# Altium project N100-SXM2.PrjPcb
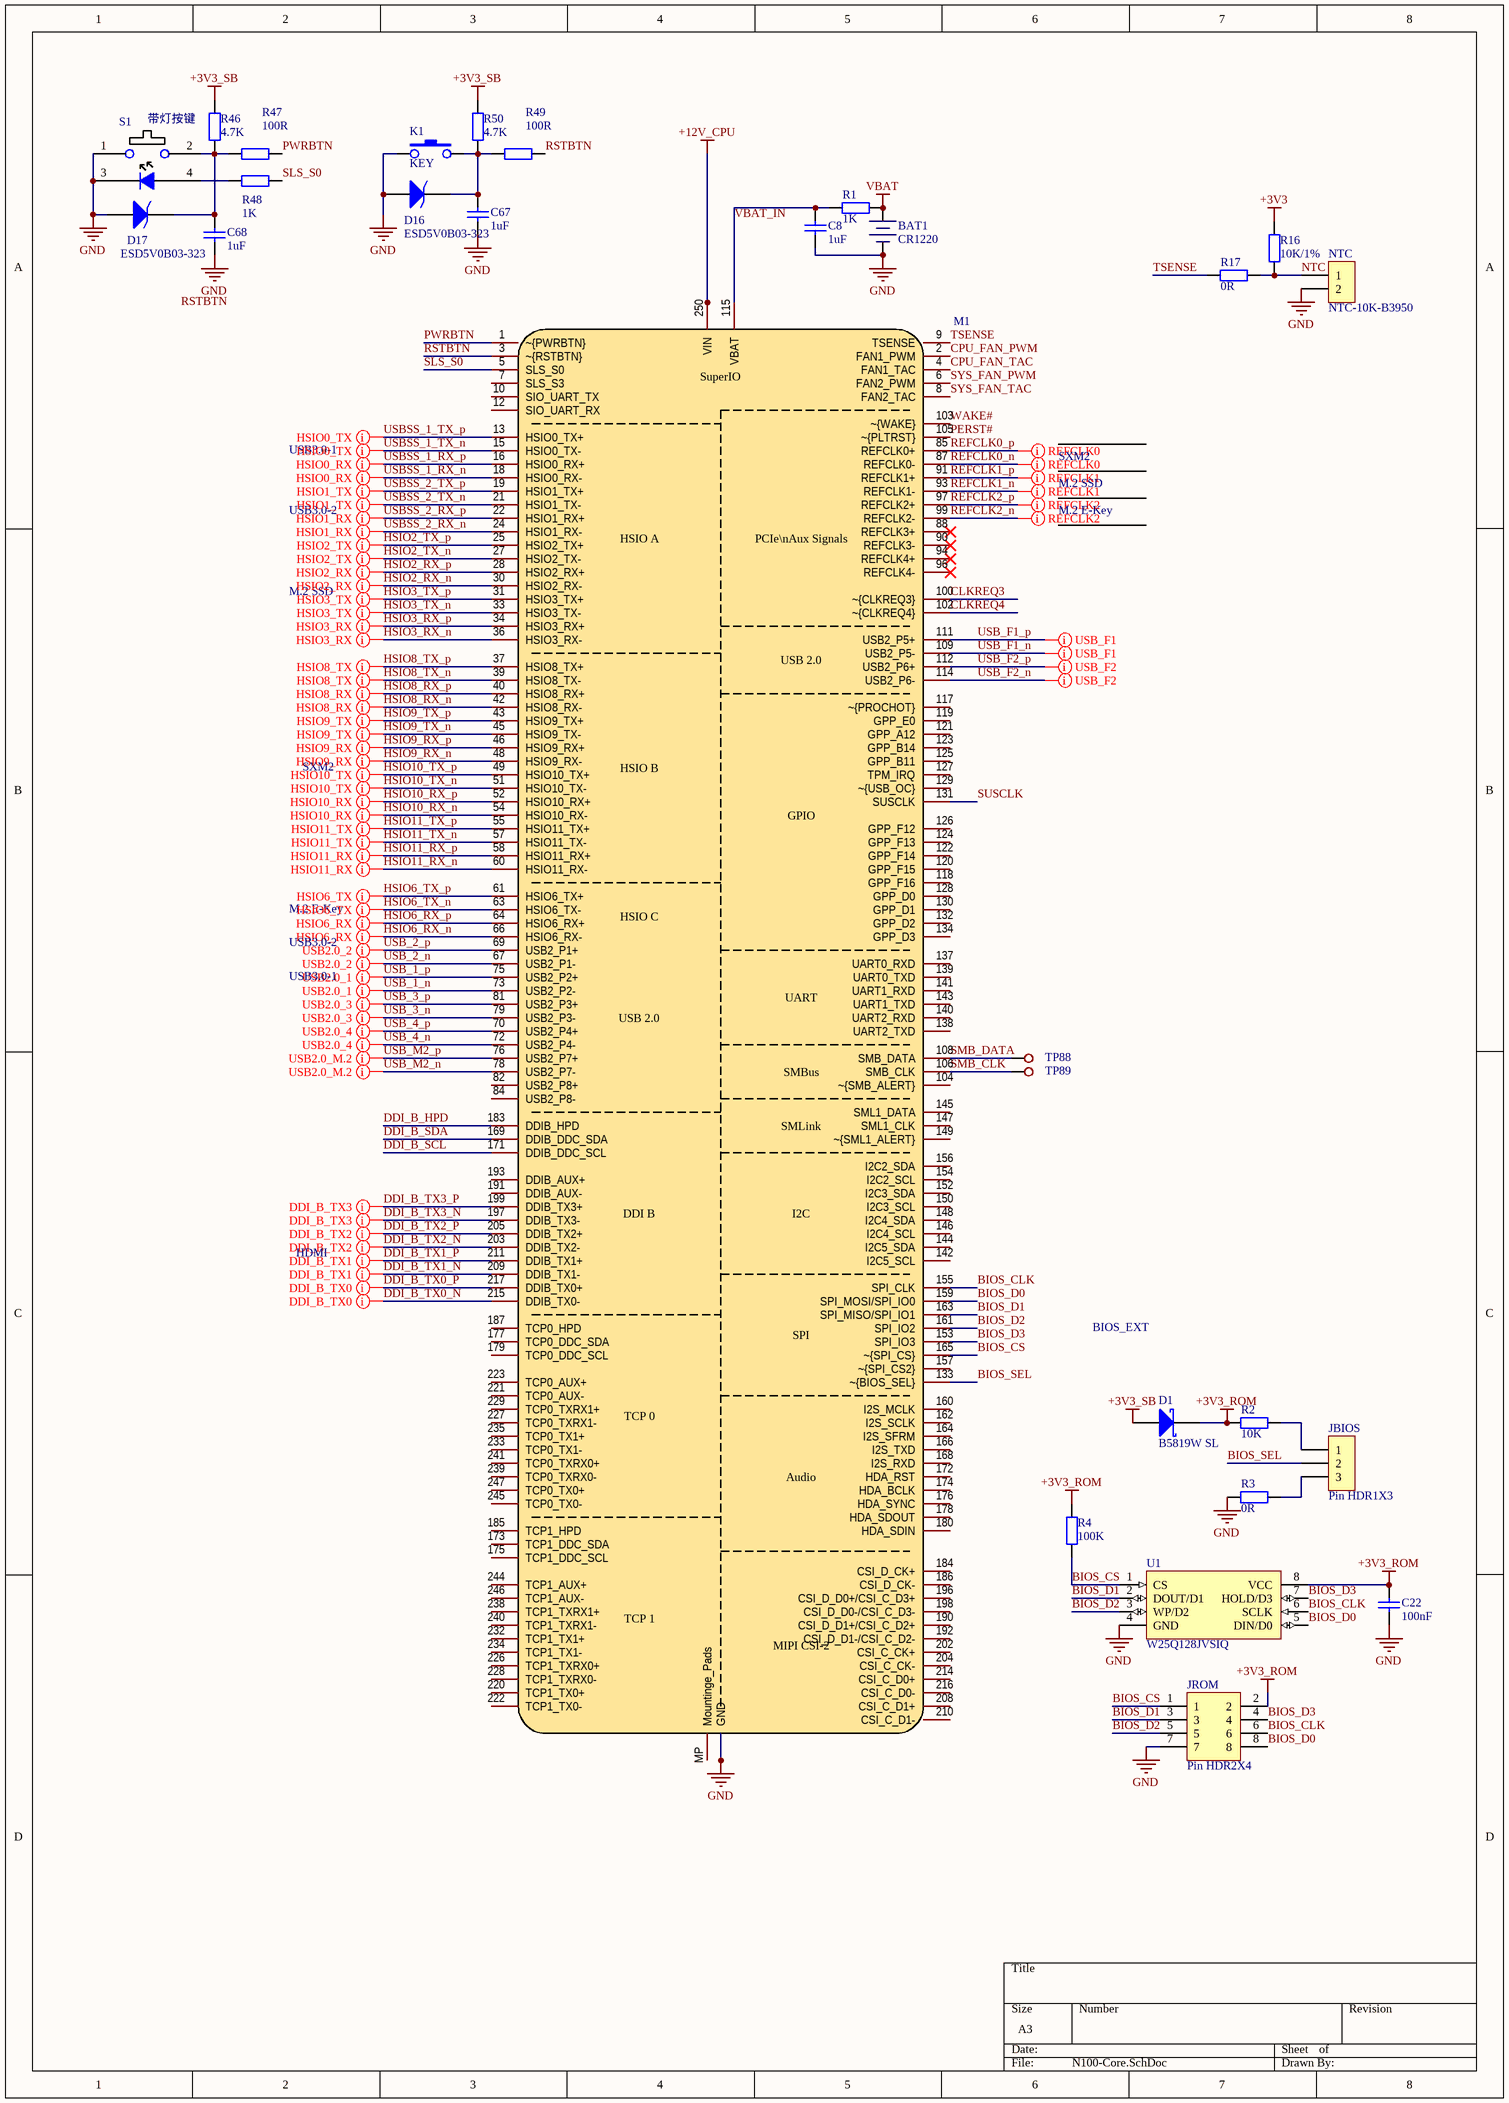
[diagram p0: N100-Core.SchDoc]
8 sheets, 267 parts. Net scope: global (net labels, ports and power ports of the same name join across sheets).
Board file: N100-SXM2.PcbDoc
Sheets:
  N100-Core.SchDoc
  M.2-PCIE.SchDoc
  PMU.SchDoc
  GbE.SchDoc
  USB.SchDoc
  DP-HDMI.SchDoc
  SXM-PCIE.SchDoc
  SXM-Power.SchDoc

## Sheet N100-Core.SchDoc
size A3 portrait; SheetNumber: 1; SheetTotal: 8

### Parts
BAT1  CR1220  [CR1220-A]
C8  1uF  [C1005-0402]
C22  100nF  [C1608-0603]
C67  1uF  [C1005-0402]
C68  1uF  [C1005-0402]
D1  B5819W SL  [SOD-123]
D16  ESD5V0B03-323  [SOD-323]
D17  ESD5V0B03-323  [SOD-323]
JBIOS  Pin HDR1X3  [Pin HDR1X3/2.54mm-S]
JROM  Pin HDR2X4  [Pin HDR2X4/2.54mm-S]
K1  KEY  [SMD-6X6X5]
M1  LattePanda_Mu  [ADDR0075]  (value not drawn)
NTC  NTC-10K-B3950  [Pin HDR1X2/2.54mm-S]
R1  1K  [R1005-0402]
R2  10K  [R1005-0402]
R3  0R  [R1005-0402]
R4  100K  [R1005-0402]
R16  10K/1%  [R1005-0402]
R17  0R  [R1005-0402]
R46  4.7K  [R1005-0402]
R47  100R  [R1005-0402]
R48  1K  [R1005-0402]
R49  100R  [R1005-0402]
R50  4.7K  [R1005-0402]
S1  带灯按键  [带灯按键]
TP88  TestPoint  [TP_50mil]  (value not drawn)
TP89  TestPoint  [TP_50mil]  (value not drawn)
U1  W25Q128JVSIQ  [SOP-8W]

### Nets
+3V3: R16.1
+3V3_ROM: C22.2 D1.1(K) JROM.2 R2.2 R4.1 U1.8(VCC)
+3V3_SB: D1.2(A) R46.1 R50.1
+12V_CPU: M1.250(VIN) M1.251(VIN) M1.252(VIN) M1.253(VIN) M1.254(VIN) M1.255(VIN) M1.256(VIN) M1.257(VIN) M1.258(VIN) M1.259(VIN) M1.260(VIN)
GND: BAT1.2 C8.1 C22.1 C67.1 C68.1 D16.2(A) D17.2(A) JROM.7 K1.1 M1.11(GND) M1.14(GND) M1.17(GND) M1.20(GND) M1.23(GND) M1.26(GND) M1.29(GND) M1.32(GND) M1.35(GND) M1.38(GND) M1.41(GND) M1.44(GND) M1.47(GND) M1.50(GND) M1.53(GND) M1.56(GND) M1.59(GND) M1.62(GND) M1.65(GND) M1.68(GND) M1.71(GND) M1.74(GND) M1.77(GND) M1.80(GND) M1.83(GND) M1.86(GND) M1.89(GND) M1.92(GND) M1.95(GND) M1.98(GND) M1.101(GND) M1.107(GND) M1.110(GND) M1.113(GND) M1.116(GND) M1.135(GND) M1.136(GND) M1.151(GND) M1.158(GND) M1.167(GND) M1.170(GND) M1.181(GND) M1.182(GND) M1.188(GND) M1.189(GND) M1.194(GND) M1.195(GND) M1.200(GND) M1.201(GND) M1.206(GND) M1.207(GND) M1.212(GND) M1.213(GND) M1.218(GND) M1.219(GND) M1.224(GND) M1.225(GND) M1.230(GND) M1.231(GND) M1.236(GND) M1.237(GND) M1.242(GND) M1.243(GND) M1.248(GND) M1.249(GND) NTC.2 R3.2 S1.1 S1.3 U1.4(GND)
VBAT: BAT1.1 R1.1
BIOS_CLK: JROM.6 M1.155(SPI_CLK) U1.6(SCLK)
BIOS_CS: JROM.1 M1.165(~{SPI_CS}) R4.2 U1.1(CS)
BIOS_D0: JROM.8 M1.159(SPI_MOSI/SPI_IO0) U1.5(DIN/D0)
BIOS_D1: JROM.3 M1.163(SPI_MISO/SPI_IO1) U1.2(DOUT/D1)
BIOS_D2: JROM.5 M1.161(SPI_IO2) U1.3(WP/D2)
BIOS_D3: JROM.4 M1.153(SPI_IO3) U1.7(HOLD/D3)
BIOS_SEL: JBIOS.2 M1.133(~{BIOS_SEL})
CLKREQ3: M1.100(~{CLKREQ3})
CLKREQ4: M1.102(~{CLKREQ4})
CPU_FAN_PWM: M1.2(FAN1_PWM)
CPU_FAN_TAC: M1.4(FAN1_TAC)
DDI_B_HPD: M1.183(DDIB_HPD)
DDI_B_SCL: M1.171(DDIB_DDC_SCL)
DDI_B_SDA: M1.169(DDIB_DDC_SDA)
DDI_B_TX0_N: M1.215(DDIB_TX0-)
DDI_B_TX0_P: M1.217(DDIB_TX0+)
DDI_B_TX1_N: M1.209(DDIB_TX1-)
DDI_B_TX1_P: M1.211(DDIB_TX1+)
DDI_B_TX2_N: M1.203(DDIB_TX2-)
DDI_B_TX2_P: M1.205(DDIB_TX2+)
DDI_B_TX3_N: M1.197(DDIB_TX3-)
DDI_B_TX3_P: M1.199(DDIB_TX3+)
HSIO2_RX_n: M1.30(HSIO2_RX-)
HSIO2_RX_p: M1.28(HSIO2_RX+)
HSIO2_TX_n: M1.27(HSIO2_TX-)
HSIO2_TX_p: M1.25(HSIO2_TX+)
HSIO3_RX_n: M1.36(HSIO3_RX-)
HSIO3_RX_p: M1.34(HSIO3_RX+)
HSIO3_TX_n: M1.33(HSIO3_TX-)
HSIO3_TX_p: M1.31(HSIO3_TX+)
HSIO6_RX_n: M1.66(HSIO6_RX-)
HSIO6_RX_p: M1.64(HSIO6_RX+)
HSIO6_TX_n: M1.63(HSIO6_TX-)
HSIO6_TX_p: M1.61(HSIO6_TX+)
HSIO8_RX_n: M1.42(HSIO8_RX-)
HSIO8_RX_p: M1.40(HSIO8_RX+)
HSIO8_TX_n: M1.39(HSIO8_TX-)
HSIO8_TX_p: M1.37(HSIO8_TX+)
HSIO9_RX_n: M1.48(HSIO9_RX-)
HSIO9_RX_p: M1.46(HSIO9_RX+)
HSIO9_TX_n: M1.45(HSIO9_TX-)
HSIO9_TX_p: M1.43(HSIO9_TX+)
HSIO10_RX_n: M1.54(HSIO10_RX-)
HSIO10_RX_p: M1.52(HSIO10_RX+)
HSIO10_TX_n: M1.51(HSIO10_TX-)
HSIO10_TX_p: M1.49(HSIO10_TX+)
HSIO11_RX_n: M1.60(HSIO11_RX-)
HSIO11_RX_p: M1.58(HSIO11_RX+)
HSIO11_TX_n: M1.57(HSIO11_TX-)
HSIO11_TX_p: M1.55(HSIO11_TX+)
NTC: NTC.1 R16.2 R17.1
PERST#: M1.105(~{PLTRST})
PWRBTN: M1.1(~{PWRBTN}) R47.1
REFCLK0_n: M1.87(REFCLK0-)
REFCLK0_p: M1.85(REFCLK0+)
REFCLK1_n: M1.93(REFCLK1-)
REFCLK1_p: M1.91(REFCLK1+)
REFCLK2_n: M1.99(REFCLK2-)
REFCLK2_p: M1.97(REFCLK2+)
RSTBTN: M1.3(~{RSTBTN}) R49.1
SLS_S0: M1.5(SLS_S0) R48.1
SMB_CLK: M1.106(SMB_CLK) TP89.1
SMB_DATA: M1.108(SMB_DATA) TP88.1
SUSCLK: M1.131(SUSCLK)
SYS_FAN_PWM: M1.6(FAN2_PWM)
SYS_FAN_TAC: M1.8(FAN2_TAC)
TSENSE: M1.9(TSENSE) R17.2
USB_1_n: M1.73(USB2_P2-)
USB_1_p: M1.75(USB2_P2+)
USB_2_n: M1.67(USB2_P1-)
USB_2_p: M1.69(USB2_P1+)
USB_3_n: M1.79(USB2_P3-)
USB_3_p: M1.81(USB2_P3+)
USB_4_n: M1.72(USB2_P4-)
USB_4_p: M1.70(USB2_P4+)
USB_F1_n: M1.109(USB2_P5-)
USB_F1_p: M1.111(USB2_P5+)
USB_F2_n: M1.114(USB2_P6-)
USB_F2_p: M1.112(USB2_P6+)
USB_M2_n: M1.78(USB2_P7-)
USB_M2_p: M1.76(USB2_P7+)
USBSS_1_RX_n: M1.18(HSIO0_RX-)
USBSS_1_RX_p: M1.16(HSIO0_RX+)
USBSS_1_TX_n: M1.15(HSIO0_TX-)
USBSS_1_TX_p: M1.13(HSIO0_TX+)
USBSS_2_RX_n: M1.24(HSIO1_RX-)
USBSS_2_RX_p: M1.22(HSIO1_RX+)
USBSS_2_TX_n: M1.21(HSIO1_TX-)
USBSS_2_TX_p: M1.19(HSIO1_TX+)
VBAT_IN: C8.2 M1.115(VBAT) R1.2
WAKE#: M1.103(~{WAKE})
NetC67_2: C67.2 D16.1(K) K1.4 R49.2 R50.2
NetC68_2: C68.2 D17.1(K) R46.2 R47.2 S1.2
NetJBIOS_1: JBIOS.1 R2.1
NetJBIOS_3: JBIOS.3 R3.1
NetR48_2: R48.2 S1.4

Not connected (* = marked no-connect by the designer): M1 7(SLS_S3) 10(SIO_UART_TX) 12(SIO_UART_RX) 82(USB2_P8+) 84(USB2_P8-) 88(REFCLK3+)* 90(REFCLK3-)* 94(REFCLK4+)* 96(REFCLK4-)* 104(~{SMB_ALERT}) 117(~{PROCHOT}) 118(GPP_F16) 119(GPP_E0) 120(GPP_F15) 121(GPP_A12) 122(GPP_F14) 123(GPP_B14) 124(GPP_F13) 125(GPP_B11) 126(GPP_F12) 127(TPM_IRQ) 128(GPP_D0) 129(~{USB_OC}) 130(GPP_D1) 132(GPP_D2) 134(GPP_D3) 137(UART0_RXD) 138(UART2_TXD) 139(UART0_TXD) 140(UART2_RXD) 141(UART1_RXD) 142(I2C5_SCL) 143(UART1_TXD) 144(I2C5_SDA) 145(SML1_DATA) 146(I2C4_SCL) 147(SML1_CLK) 148(I2C4_SDA) 149(~{SML1_ALERT}) 150(I2C3_SCL) 152(I2C3_SDA) 154(I2C2_SCL) 156(I2C2_SDA) 157(~{SPI_CS2}) 160(I2S_MCLK) 162(I2S_SCLK) 164(I2S_SFRM) 166(I2S_TXD) 168(I2S_RXD) 172(HDA_RST) 173(TCP1_DDC_SDA) 174(HDA_BCLK) 175(TCP1_DDC_SCL) 176(HDA_SYNC) 177(TCP0_DDC_SDA) 178(HDA_SDOUT) 179(TCP0_DDC_SCL) 180(HDA_SDIN) 184(CSI_D_CK+) 185(TCP1_HPD) 186(CSI_D_CK-) 187(TCP0_HPD) 190(CSI_D_D1+/CSI_C_D2+) 191(DDIB_AUX-) 192(CSI_D_D1-/CSI_C_D2-) 193(DDIB_AUX+) 196(CSI_D_D0+/CSI_C_D3+) 198(CSI_D_D0-/CSI_C_D3-) 202(CSI_C_CK+) 204(CSI_C_CK-) 208(CSI_C_D1+) 210(CSI_C_D1-) 214(CSI_C_D0+) 216(CSI_C_D0-) 220(TCP1_TX0+) 221(TCP0_AUX-) 222(TCP1_TX0-) 223(TCP0_AUX+) 226(TCP1_TXRX0+) 227(TCP0_TXRX1-) 228(TCP1_TXRX0-) 229(TCP0_TXRX1+) 232(TCP1_TX1+) 233(TCP0_TX1-) 234(TCP1_TX1-) 235(TCP0_TX1+) 238(TCP1_TXRX1+) 239(TCP0_TXRX0-) 240(TCP1_TXRX1-) 241(TCP0_TXRX0+) 244(TCP1_AUX+) 245(TCP0_TX0-) 246(TCP1_AUX-) 247(TCP0_TX0+) MP(Mountinge_Pads)

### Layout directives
differential pair: HSIO2_RX_n, HSIO2_RX_p, HSIO2_TX_n, HSIO2_TX_p, HSIO3_RX_n, HSIO3_RX_p, HSIO3_TX_n, HSIO3_TX_p, HSIO6_RX_n, HSIO6_RX_p, HSIO6_TX_n, HSIO6_TX_p, HSIO8_RX_n, HSIO8_RX_p, HSIO8_TX_n, HSIO8_TX_p, HSIO9_RX_n, HSIO9_RX_p, HSIO9_TX_n, HSIO9_TX_p, HSIO10_RX_n, HSIO10_RX_p, HSIO10_TX_n, HSIO10_TX_p, HSIO11_RX_n, HSIO11_RX_p, HSIO11_TX_n, HSIO11_TX_p, REFCLK0_n, REFCLK0_p, REFCLK1_n, REFCLK1_p, REFCLK2_n, REFCLK2_p, USB_1_n, USB_1_p, USB_2_n, USB_2_p, USB_3_n, USB_3_p, USB_4_n, USB_4_p, USB_F1_n, USB_F1_p, USB_F2_n, USB_F2_p, USB_M2_n, USB_M2_p, USBSS_1_RX_n, USBSS_1_RX_p, USBSS_1_TX_n, USBSS_1_TX_p, USBSS_2_RX_n, USBSS_2_RX_p, USBSS_2_TX_n, USBSS_2_TX_p
net class HSIO: HSIO2_RX_n, HSIO2_RX_p, HSIO2_TX_n, HSIO2_TX_p, HSIO3_RX_n, HSIO3_RX_p, HSIO3_TX_n, HSIO3_TX_p, HSIO6_RX_n, HSIO6_RX_p, HSIO6_TX_n, HSIO6_TX_p, HSIO8_RX_n, HSIO8_RX_p, HSIO8_TX_n, HSIO8_TX_p, HSIO9_RX_n, HSIO9_RX_p, HSIO9_TX_n, HSIO9_TX_p, HSIO10_RX_n, HSIO10_RX_p, HSIO10_TX_n, HSIO10_TX_p, HSIO11_RX_n, HSIO11_RX_p, HSIO11_TX_n, HSIO11_TX_p, REFCLK0_n, REFCLK0_p, REFCLK1_n, REFCLK1_p, REFCLK2_n, REFCLK2_p, USB_1_n, USB_1_p, USB_2_n, USB_2_p, USB_3_n, USB_3_p, USB_4_n, USB_4_p, USB_F1_n, USB_F1_p, USB_F2_n, USB_F2_p, USB_M2_n, USB_M2_p, USBSS_1_RX_n, USBSS_1_RX_p, USBSS_1_TX_n, USBSS_1_TX_p, USBSS_2_RX_n, USBSS_2_RX_p, USBSS_2_TX_n, USBSS_2_TX_p
differential pair; net class HSIO: DDI_B_TX0_N, DDI_B_TX0_P, DDI_B_TX1_N, DDI_B_TX1_P, DDI_B_TX2_N, DDI_B_TX2_P, DDI_B_TX3_N, DDI_B_TX3_P

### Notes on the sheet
- USB3.0-1
- SXM2
- M.2 SSD
- USB3.0-2
- M.2 E-Key
- HDMI
- BIOS_EXT
- Labels drawn without touching a wire or pin: RSTBTN

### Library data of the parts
C8 C67 C68 = C1005-0402
C22 = C1608-0603: Value: 1uF
D1 = Schottky Diode
D16 D17 = TVS Diode
M1 = LattePanda_Mu: A micro computing module with x86 processer, RAM and eMMC.; ki_keywords: lattepanda mu x86 compute module; ki_fp_filters: *LattePanda*; Add into BOM: yes
NTC = Pin HDR1X2
R1-R4 R16 R17 R46-R50 = R1608-0603: Resistor
S1 = 带灯按键: https://item.taobao.com/item.htm?id=677075017698
U1 = GD25Q40CTIG

## Sheet M.2-PCIE.SchDoc
size A3; SheetNumber: 2; SheetTotal: 8
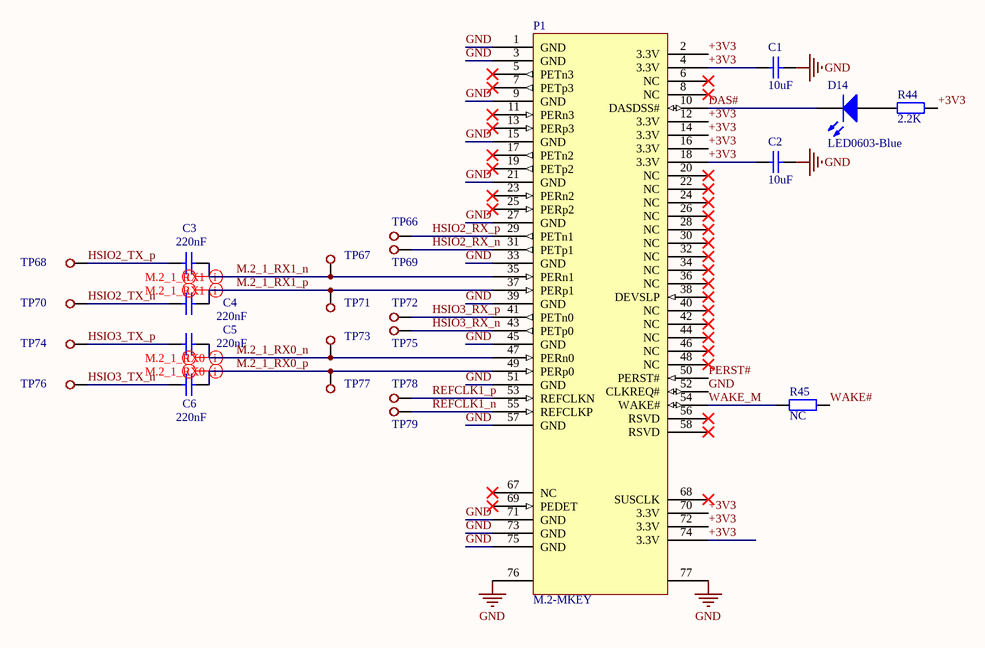
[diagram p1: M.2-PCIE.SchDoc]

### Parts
C1  10uF  [C1608-0603]
C2  10uF  [C1608-0603]
C3  220nF  [C1005-0402]
C4  220nF  [C1005-0402]
C5  220nF  [C1005-0402]
C6  220nF  [C1005-0402]
D14  LED0603-Blue  [LED0603-B]
P1  M.2-MKEY  [M.2-M]
R44  2.2K  [R1005-0402]
R45  NC  [R1005-0402]
TP66  TestPoint  [TP_HS]  (value not drawn)
TP67  TestPoint  [TP_HS]  (value not drawn)
TP68  TestPoint  [TP_HS]  (value not drawn)
TP69  TestPoint  [TP_HS]  (value not drawn)
TP70  TestPoint  [TP_HS]  (value not drawn)
TP71  TestPoint  [TP_HS]  (value not drawn)
TP72  TestPoint  [TP_HS]  (value not drawn)
TP73  TestPoint  [TP_HS]  (value not drawn)
TP74  TestPoint  [TP_HS]  (value not drawn)
TP75  TestPoint  [TP_HS]  (value not drawn)
TP76  TestPoint  [TP_HS]  (value not drawn)
TP77  TestPoint  [TP_HS]  (value not drawn)
TP78  TestPoint  [TP_HS]  (value not drawn)
TP79  TestPoint  [TP_HS]  (value not drawn)

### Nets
+3V3: C1.2 C2.2 P1.2(3.3V) P1.4(3.3V) P1.12(3.3V) P1.14(3.3V) P1.16(3.3V) P1.18(3.3V) P1.70(3.3V) P1.72(3.3V) P1.74(3.3V) R44.1
GND: C1.1 C2.1 P1.1(GND) P1.3(GND) P1.9(GND) P1.15(GND) P1.21(GND) P1.27(GND) P1.33(GND) P1.39(GND) P1.45(GND) P1.51(GND) P1.52(CLKREQ#) P1.57(GND) P1.71(GND) P1.73(GND) P1.75(GND) P1.76 P1.77
DAS#: D14.1(K) P1.10(DASDSS#)
HSIO2_RX_n: P1.31(PETp1) TP69.1
HSIO2_RX_p: P1.29(PETn1) TP66.1
HSIO2_TX_n: C4.2 TP70.1
HSIO2_TX_p: C3.2 TP68.1
HSIO3_RX_n: P1.43(PETp0) TP75.1
HSIO3_RX_p: P1.41(PETn0) TP72.1
HSIO3_TX_n: C6.2 TP76.1
HSIO3_TX_p: C5.2 TP74.1
M.2_1_RX0_n: C5.1 P1.47(PERn0) TP73.1
M.2_1_RX0_p: C6.1 P1.49(PERp0) TP77.1
M.2_1_RX1_n: C3.1 P1.35(PERn1) TP67.1
M.2_1_RX1_p: C4.1 P1.37(PERp1) TP71.1
PERST#: P1.50(PERST#)
REFCLK1_n: P1.55(REFCLKP) TP79.1
REFCLK1_p: P1.53(REFCLKN) TP78.1
WAKE#: R45.1
WAKE_M: P1.54(WAKE#) R45.2
NetD14_2: D14.2(A) R44.2

Not connected (* = marked no-connect by the designer): P1 5(PETn3)* 6(NC)* 7(PETp3)* 8(NC)* 11(PERn3)* 13(PERp3)* 17(PETn2)* 19(PETp2)* 20(NC)* 22(NC)* 23(PERn2)* 24(NC)* 25(PERp2)* 26(NC)* 28(NC)* 30(NC)* 32(NC)* 34(NC)* 36(NC)* 38(DEVSLP)* 40(NC)* 42(NC)* 44(NC)* 46(NC)* 48(NC)* 56(RSVD)* 58(RSVD)* 67(NC)* 68(SUSCLK)* 69(PEDET)*

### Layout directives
differential pair: M.2_1_RX0_n, M.2_1_RX0_p, M.2_1_RX1_n, M.2_1_RX1_p
net class HSIO: M.2_1_RX0_n, M.2_1_RX0_p, M.2_1_RX1_n, M.2_1_RX1_p

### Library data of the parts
C1 C2 = C1608-0603: Value: 1uF
C3-C6 = C1005-0402: Value: 1uF
D14 = LED0603-B
P1 = M.2-MKEY: Socket 3 PCIe-based Module
R44 R45 = R1005-0402: Resistor
TP66-TP79 = TestPoint_HS

## Sheet PMU.SchDoc
size A3; SheetNumber: 3; SheetTotal: 8
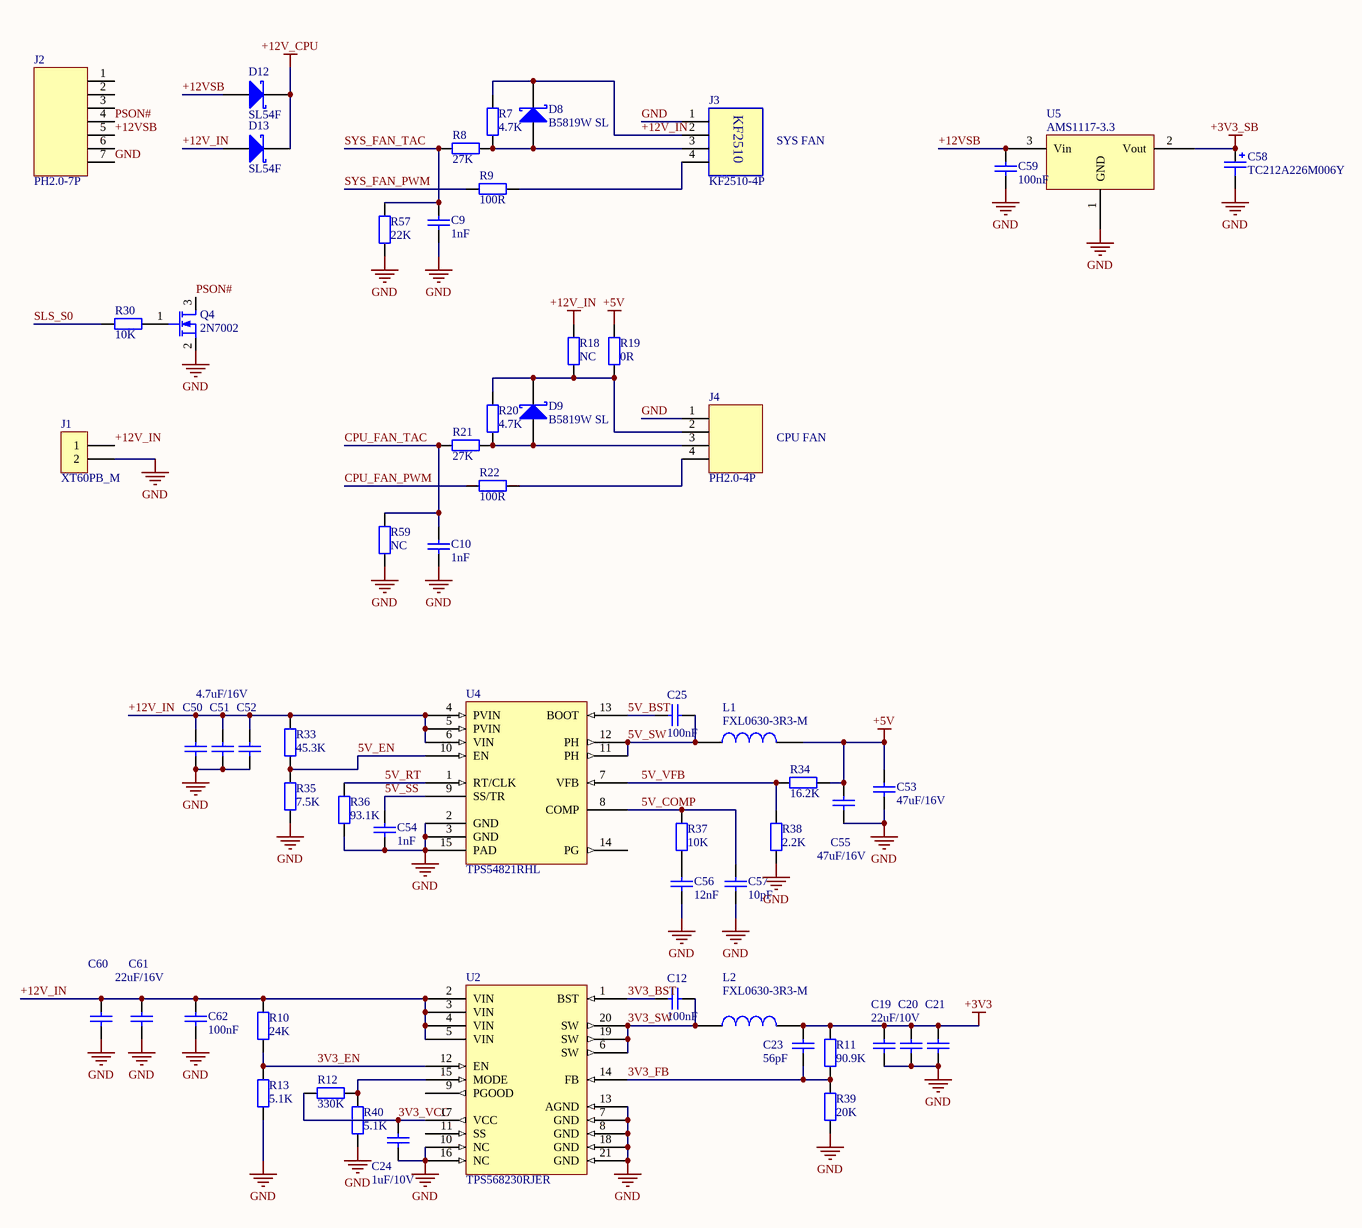
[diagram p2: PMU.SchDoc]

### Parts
C9  1nF  [C1005-0402]
C10  1nF  [C1005-0402]
C12  100nF  [C1005-0402]
C19  22uF/10V  [C2012-0805/Y1.2]
C20  22uF/10V  [C2012-0805/Y1.2]  (value not drawn)
C21  22uF/10V  [C2012-0805/Y1.2]  (value not drawn)
C23  56pF  [C1005-0402]
C24  1uF/10V  [C1005-0402]
C25  100nF  [C1005-0402]
C50  4.7uF/16V  [C2012-0805/Y1.2]  (value not drawn)
C51  4.7uF/16V  [C2012-0805/Y1.2]  (value not drawn)
C52  4.7uF/16V  [C2012-0805/Y1.2]
C53  47uF/16V  [C3225-1210]
C54  1nF  [C1005-0402]
C55  47uF/16V  [C3225-1210]
C56  12nF  [C1005-0402]
C57  10pF  [C1005-0402]
C58  TC212A226M006Y  [TC3216-1206]
C59  100nF  [C1608-0603]
C60  22uF/16V  [C3216-1206]  (value not drawn)
C61  22uF/16V  [C3216-1206]
C62  100nF  [C1005-0402]
D8  B5819W SL  [SOD-123]
D9  B5819W SL  [SOD-123]
D12  SL54F  [SMAF]
D13  SL54F  [SMAF]
J1  XT60PB_M  [XT60PB-M]
J2  PH2.0-7P  [PH2.0-7P]
J3  KF2510-4P  [KF2510-4P]
J4  PH2.0-4P  [PH2.0-4P]
L1  FXL0630-3R3-M  [06030]
L2  FXL0630-3R3-M  [06030]
Q4  2N7002  [SOT-23-N]
R7  4.7K  [R1005-0402]
R8  27K  [R1005-0402]
R9  100R  [R1005-0402]
R10  24K  [R1005-0402]
R11  90.9K  [R1005-0402]
R12  330K  [R1005-0402]
R13  5.1K  [R1005-0402]
R18  NC  [R1608-0603]
R19  0R  [R1608-0603]
R20  4.7K  [R1005-0402]
R21  27K  [R1005-0402]
R22  100R  [R1005-0402]
R30  10K  [R1005-0402]
R33  45.3K  [R1005-0402]
R34  16.2K  [R1005-0402]
R35  7.5K  [R1005-0402]
R36  93.1K  [R1005-0402]
R37  10K  [R1005-0402]
R38  2.2K  [R1005-0402]
R39  20K  [R1005-0402]
R40  5.1K  [R1005-0402]
R57  22K  [R1005-0402]
R59  NC  [R1005-0402]
U2  TPS568230RJER  [RJE0020A]
U4  TPS54821RHL  [RHL14]
U5  AMS1117-3.3  [SOT223]

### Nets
+3V3: C19.2 C20.2 C21.2 C23.2 L2.2 R11.2
+3V3_SB: C58.1 U5.2(Vout)
+5V: C53.2 C55.2 L1.2 R19.1 R34.2
+12V_CPU: D12.1(K) D13.1(K)
+12V_IN: C50.2 C51.2 C52.2 C60.2 C61.2 C62.2 D8.1(K) D13.2(A) J1.1 J3.2 R7.1 R10.2 R18.1 R33.1 U2.2(VIN) U2.3(VIN) U2.4(VIN) U2.5(VIN) U4.4(PVIN) U4.5(PVIN) U4.6(VIN)
GND: C9.1 C10.1 C19.1 C20.1 C21.1 C24.1 C50.1 C51.1 C52.1 C53.1 C54.1 C55.1 C56.1 C57.1 C58.2 C59.1 C60.1 C61.1 C62.1 J1.2 J2.7 J3.1 J4.1 Q4.2(S) R13.1 R35.2 R36.2 R38.1 R39.1 R40.2 R57.2 R59.2 U2.7(GND) U2.8(GND) U2.10(NC) U2.13(AGND) U2.16(NC) U2.18(GND) U2.21(GND) U4.2(GND) U4.3(GND) U4.15(PAD) U5.1(GND)
3V3_BST: C12.2 U2.1(BST)
3V3_EN: R10.1 R13.2 U2.12(EN)
3V3_FB: C23.1 R11.1 R39.2 U2.14(FB)
3V3_SW: C12.1 L2.1 U2.6(SW) U2.19(SW) U2.20(SW)
3V3_VCC: C24.2 R12.2 U2.17(VCC)
5V_BST: C25.2 U4.13(BOOT)
5V_COMP: C57.2 R37.1 U4.8(COMP)
5V_EN: R33.2 R35.1 U4.10(EN)
5V_RT: R36.1 U4.1(RT/CLK)
5V_SS: C54.2 U4.9(SS/TR)
5V_SW: C25.1 L1.1 U4.11(PH) U4.12(PH)
5V_VFB: R34.1 R38.2 U4.7(VFB)
+12VSB: C59.2 D12.2(A) J2.5 U5.3(Vin)
CPU_FAN_PWM: R22.2
CPU_FAN_TAC: C10.2 R21.2 R59.1
PSON#: J2.4 Q4.3(D)
SLS_S0: R30.2
SYS_FAN_PWM: R9.2
SYS_FAN_TAC: C9.2 R8.2 R57.1
NetC56_2: C56.2 R37.2
NetD8_2: D8.2(A) J3.3 R7.2 R8.1
NetD9_1: D9.1(K) J4.2 R18.2 R19.2 R20.1
NetD9_2: D9.2(A) J4.3 R20.2 R21.1
NetJ3_4: J3.4 R9.1
NetJ4_4: J4.4 R22.1
NetQ4_1: Q4.1(G) R30.1
NetR12_1: R12.1 R40.1 U2.15(MODE)

Not connected (* = marked no-connect by the designer): J2 1 2 3 6; U2 9(PGOOD) 11(SS); U4 14(PG)

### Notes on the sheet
- SYS FAN
- CPU FAN

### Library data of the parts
C9 C10 C59 = C1608-0603: Value: 1uF
C12 C23-C25 C54 C56 C57 C62 = C1005-0402: Value: 1uF
C19-C21 C50-C52 = C2012-0805: Value: 1uF
C53 C55 = C3225-1210: Value: 10uF
C58 = TC3216-1206: Tantalum Capacitor; Value: 10uF
C60 C61 = C3216-1206: Value: 10uF
D8 D9 D12 D13 = Schottky Diode
J1 = Pin HDR1X2
L1 L2 = INDUCTOR
Q4 = AO3400A: N-Channel MOSFET
R7-R13 R18-R22 R30 R33-R40 R57 R59 = R1608-0603: Resistor
U2 = TPS568230
U4 = TPS54821
U5 = AMS1117: 三端稳压芯片

## Sheet GbE.SchDoc
size A3; SheetNumber: 4; SheetTotal: 8
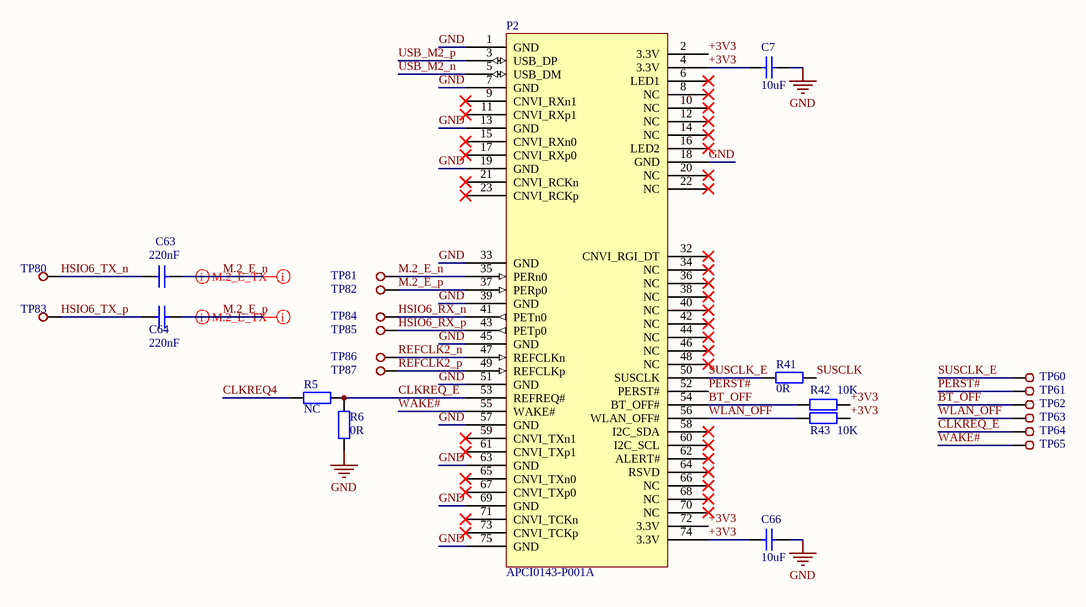
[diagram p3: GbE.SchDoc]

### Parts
C7  10uF  [C1608-0603]
C63  220nF  [C1005-0402]
C64  220nF  [C1005-0402]
C66  10uF  [C1608-0603]
P2  APCI0143-P001A  [APCI0143-P001A]
R5  NC  [R1005-0402]
R6  0R  [R1005-0402]
R41  0R  [R1005-0402]
R42  10K  [R1005-0402]
R43  10K  [R1005-0402]
TP60  TestPoint  [TP_50mil]  (value not drawn)
TP61  TestPoint  [TP_50mil]  (value not drawn)
TP62  TestPoint  [TP_50mil]  (value not drawn)
TP63  TestPoint  [TP_50mil]  (value not drawn)
TP64  TestPoint  [TP_50mil]  (value not drawn)
TP65  TestPoint  [TP_50mil]  (value not drawn)
TP80  TestPoint  [TP_HS]  (value not drawn)
TP81  TestPoint  [TP_HS]  (value not drawn)
TP82  TestPoint  [TP_HS]  (value not drawn)
TP83  TestPoint  [TP_HS]  (value not drawn)
TP84  TestPoint  [TP_HS]  (value not drawn)
TP85  TestPoint  [TP_HS]  (value not drawn)
TP86  TestPoint  [TP_HS]  (value not drawn)
TP87  TestPoint  [TP_HS]  (value not drawn)

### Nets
+3V3: C7.2 C66.2 P2.2(3.3V) P2.4(3.3V) P2.72(3.3V) P2.74(3.3V) R42.1 R43.1
GND: C7.1 C66.1 P2.1(GND) P2.7(GND) P2.13(GND) P2.18(GND) P2.19(GND) P2.33(GND) P2.39(GND) P2.45(GND) P2.51(GND) P2.57(GND) P2.63(GND) P2.69(GND) P2.75(GND) R6.2
BT_OFF: P2.54(BT_OFF#) R42.2 TP62.1
CLKREQ4: R5.2
CLKREQ_E: P2.53(REFREQ#) R5.1 R6.1 TP64.1
HSIO6_RX_n: P2.41(PETn0) TP84.1
HSIO6_RX_p: P2.43(PETp0) TP85.1
HSIO6_TX_n: C63.2 TP80.1
HSIO6_TX_p: C64.2 TP83.1
M.2_E_n: C63.1 P2.35(PERn0) TP81.1
M.2_E_p: C64.1 P2.37(PERp0) TP82.1
PERST#: P2.52(PERST#) TP61.1
REFCLK2_n: P2.47(REFCLKn) TP86.1
REFCLK2_p: P2.49(REFCLKp) TP87.1
SUSCLK: R41.1
SUSCLK_E: P2.50(SUSCLK) R41.2 TP60.1
USB_M2_n: P2.5(USB_DM)
USB_M2_p: P2.3(USB_DP)
WAKE#: P2.55(WAKE#) TP65.1
WLAN_OFF: P2.56(WLAN_OFF#) R43.2 TP63.1

Not connected (* = marked no-connect by the designer): P2 6(LED1)* 8(NC)* 9(CNVI_RXn1)* 10(NC)* 11(CNVI_RXp1)* 12(NC)* 14(NC)* 15(CNVI_RXn0)* 16(LED2)* 17(CNVI_RXp0)* 20(NC)* 21(CNVI_RCKn)* 22(NC)* 23(CNVI_RCKp)* 32(CNVI_RGI_DT)* 34(NC)* 36(NC)* 38(NC)* 40(NC)* 42(NC)* 44(NC)* 46(NC)* 48(NC)* 58(I2C_SDA)* 59(CNVI_TXn1)* 60(I2C_SCL)* 61(CNVI_TXp1)* 62(ALERT#)* 64(RSVD)* 65(CNVI_TXn0)* 66(NC)* 67(CNVI_TXp0)* 68(NC)* 70(NC)* 71(CNVI_TCKn)* 73(CNVI_TCKp)*

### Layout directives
differential pair: M.2_E_n, M.2_E_p
net class HSIO: M.2_E_n, M.2_E_p

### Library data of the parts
C7 C66 = C1608-0603: Value: 1uF
C63 C64 = C1005-0402: Value: 1uF
P2 = APCI0143-P001A: Socket 1 PCIe-based Module
R5 R6 R41-R43 = R1005-0402: Resistor
TP80-TP87 = TestPoint_HS

## Sheet USB.SchDoc
size A3; SheetNumber: 5; SheetTotal: 8
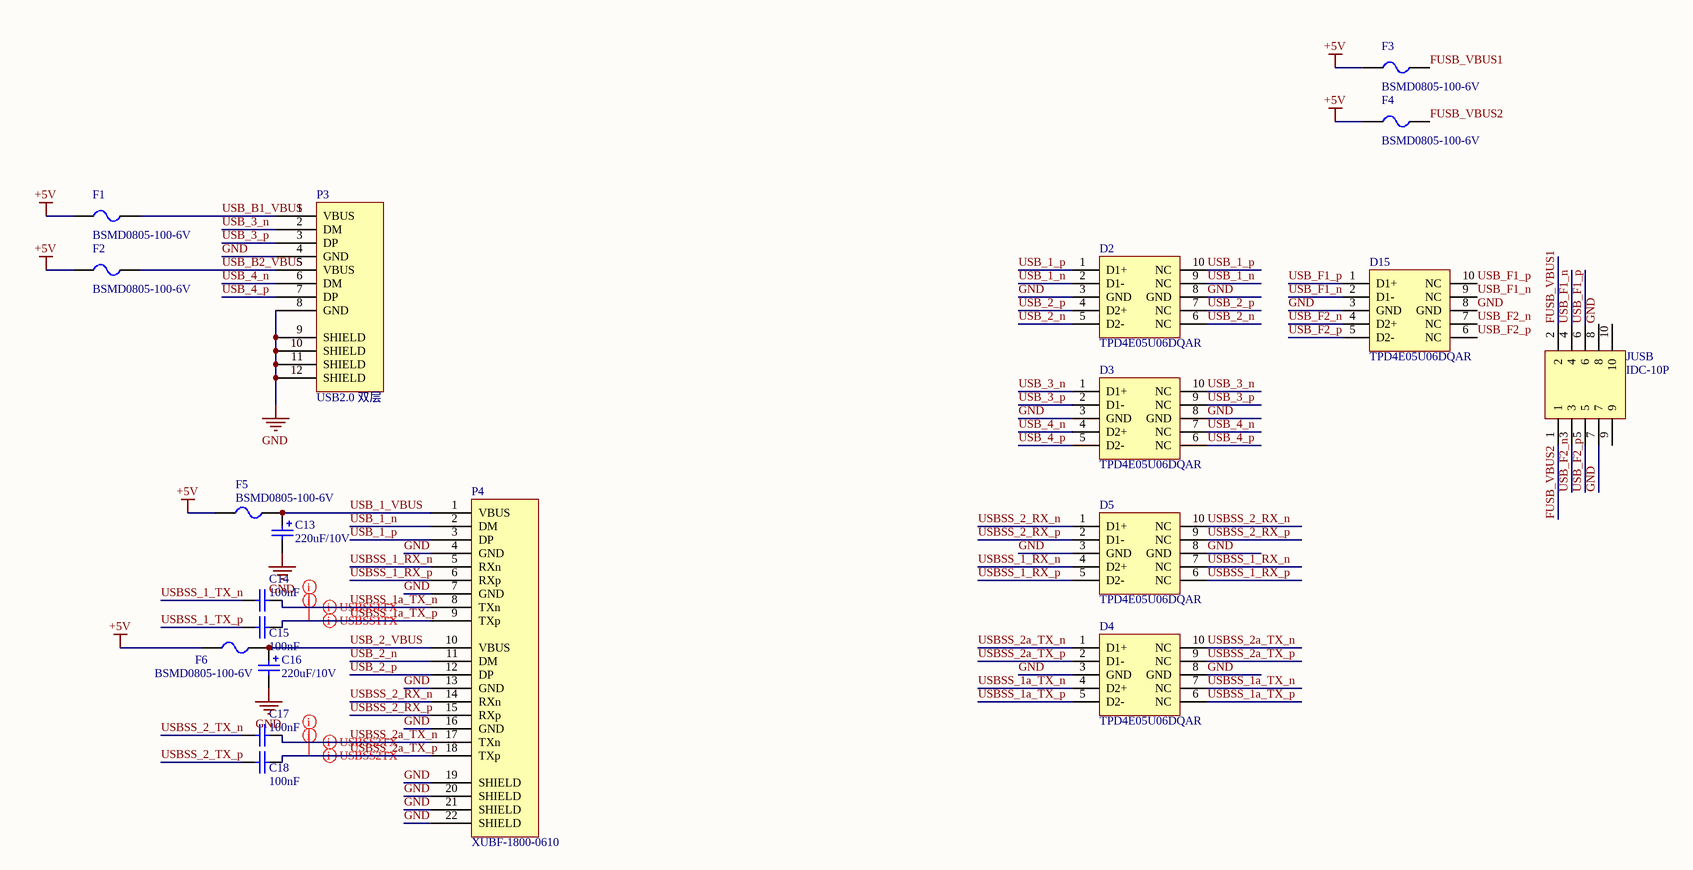
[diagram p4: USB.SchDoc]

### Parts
C13  220uF/10V  [C6-6X6MM]
C14  100nF  [C1005-0402]
C15  100nF  [C1005-0402]
C16  220uF/10V  [C6-6X6MM]
C17  100nF  [C1005-0402]
C18  100nF  [C1005-0402]
D2  TPD4E05U06DQAR  [DQA0010B]
D3  TPD4E05U06DQAR  [DQA0010B]
D4  TPD4E05U06DQAR  [DQA0010B]
D5  TPD4E05U06DQAR  [DQA0010B]
D15  TPD4E05U06DQAR  [DQA0010B]
F1  BSMD0805-100-6V  [FU 0402]
F2  BSMD0805-100-6V  [FU 0402]
F3  BSMD0805-100-6V  [FU 0402]
F4  BSMD0805-100-6V  [FU 0402]
F5  BSMD0805-100-6V  [FU 0402]
F6  BSMD0805-100-6V  [FU 0402]
JUSB  IDC-10P  [IDC2.54-10P]
P3  USB2.0 双层  [USB-269-BRW]
P4  XUBF-1800-0610  [XUBF-1800-0610]

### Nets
+5V: F1.1 F2.1 F3.1 F4.1 F5.1 F6.1
GND: C13.2 C16.2 D2.3(GND) D2.8(GND) D3.3(GND) D3.8(GND) D4.3(GND) D4.8(GND) D5.3(GND) D5.8(GND) D15.3(GND) D15.8(GND) JUSB.7 JUSB.8 P3.4(GND) P3.8(GND) P3.9(SHIELD) P3.10(SHIELD) P3.11(SHIELD) P3.12(SHIELD) P4.4(GND) P4.7(GND) P4.13(GND) P4.16(GND) P4.19(SHIELD) P4.20(SHIELD) P4.21(SHIELD) P4.22(SHIELD)
FUSB_VBUS1: F3.2 JUSB.2
FUSB_VBUS2: F4.2 JUSB.1
USB_1_n: D2.2(D1-) D2.9(NC) P4.2(DM)
USB_1_p: D2.1(D1+) D2.10(NC) P4.3(DP)
USB_1_VBUS: C13.1 F5.2 P4.1(VBUS)
USB_2_n: D2.5(D2-) D2.6(NC) P4.11(DM)
USB_2_p: D2.4(D2+) D2.7(NC) P4.12(DP)
USB_2_VBUS: C16.1 F6.2 P4.10(VBUS)
USB_3_n: D3.1(D1+) D3.10(NC) P3.2(DM)
USB_3_p: D3.2(D1-) D3.9(NC) P3.3(DP)
USB_4_n: D3.4(D2+) D3.7(NC) P3.6(DM)
USB_4_p: D3.5(D2-) D3.6(NC) P3.7(DP)
USB_B1_VBUS: F1.2 P3.1(VBUS)
USB_B2_VBUS: F2.2 P3.5(VBUS)
USB_F1_n: D15.2(D1-) D15.9(NC) JUSB.4
USB_F1_p: D15.1(D1+) D15.10(NC) JUSB.6
USB_F2_n: D15.4(D2+) D15.7(NC) JUSB.3
USB_F2_p: D15.5(D2-) D15.6(NC) JUSB.5
USBSS_1_RX_n: D5.4(D2+) D5.7(NC) P4.5(RXn)
USBSS_1_RX_p: D5.5(D2-) D5.6(NC) P4.6(RXp)
USBSS_1_TX_n: C14.2
USBSS_1_TX_p: C15.2
USBSS_1a_TX_n: C14.1 D4.4(D2+) D4.7(NC) P4.8(TXn)
USBSS_1a_TX_p: C15.1 D4.5(D2-) D4.6(NC) P4.9(TXp)
USBSS_2_RX_n: D5.1(D1+) D5.10(NC) P4.14(RXn)
USBSS_2_RX_p: D5.2(D1-) D5.9(NC) P4.15(RXp)
USBSS_2_TX_n: C17.2
USBSS_2_TX_p: C18.2
USBSS_2a_TX_n: C17.1 D4.1(D1+) D4.10(NC) P4.17(TXn)
USBSS_2a_TX_p: C18.1 D4.2(D1-) D4.9(NC) P4.18(TXp)

Not connected (* = marked no-connect by the designer): JUSB 9 10

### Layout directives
differential pair: USBSS_1a_TX_n, USBSS_1a_TX_p, USBSS_2a_TX_n, USBSS_2a_TX_p
net class HSIO: USBSS_1a_TX_n, USBSS_1a_TX_p, USBSS_2a_TX_n, USBSS_2a_TX_p

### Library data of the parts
C13 C16 = CAPPR: Aluminum Capacitor; Value: 10uF
C14 C15 C17 C18 = C1005-0402: Value: 1uF
D2-D5 D15 = TPD4E05U06
F1-F6 = FU: 贴片保险丝; 版权归属: 源创客

## Sheet DP-HDMI.SchDoc
size A3; SheetNumber: 6; SheetTotal: 8
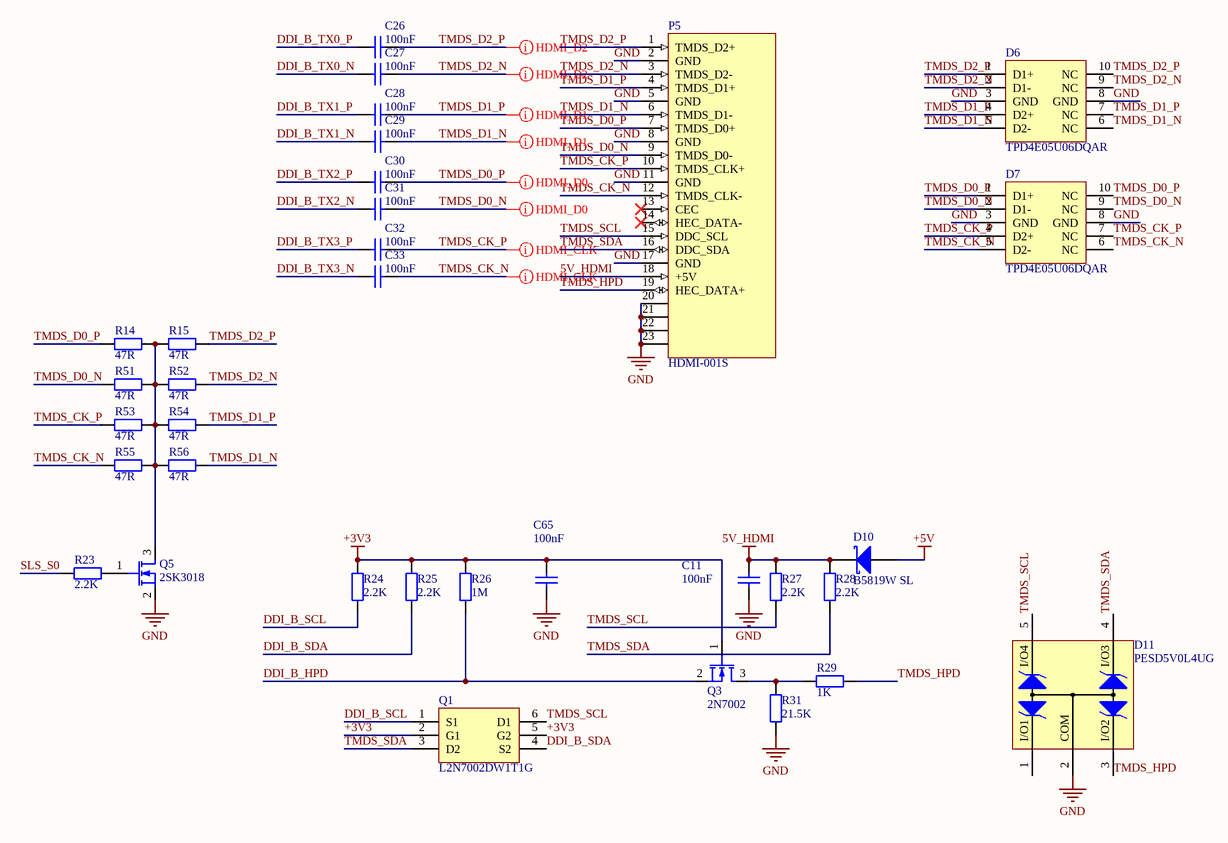
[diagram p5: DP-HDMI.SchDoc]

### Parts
C11  100nF  [C1005-0402]
C26  100nF  [C1005-0402]
C27  100nF  [C1005-0402]
C28  100nF  [C1005-0402]
C29  100nF  [C1005-0402]
C30  100nF  [C1005-0402]
C31  100nF  [C1005-0402]
C32  100nF  [C1005-0402]
C33  100nF  [C1005-0402]
C65  100nF  [C1005-0402]
D6  TPD4E05U06DQAR  [DQA0010B]
D7  TPD4E05U06DQAR  [DQA0010B]
D10  B5819W SL  [SOD-123]
D11  PESD5V0L4UG  [SC70-5]
P5  HDMI-001S  [HDMI-001S]
Q1  L2N7002DW1T1G  [SOT-363]
Q3  2N7002  [SOT-23-N]
Q5  2SK3018  [SOT-23-N]
R14  47R  [R1005-0402]
R15  47R  [R1005-0402]
R23  2.2K  [R1005-0402]
R24  2.2K  [R1005-0402]
R25  2.2K  [R1005-0402]
R26  1M  [R1005-0402]
R27  2.2K  [R1005-0402]
R28  2.2K  [R1005-0402]
R29  1K  [R1005-0402]
R31  21.5K  [R1005-0402]
R51  47R  [R1005-0402]
R52  47R  [R1005-0402]
R53  47R  [R1005-0402]
R54  47R  [R1005-0402]
R55  47R  [R1005-0402]
R56  47R  [R1005-0402]

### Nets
5V_HDMI: C11.1 D10.1(K) P5.18(+5V) R27.2 R28.2
+3V3: C65.1 Q1.2(G1) Q1.5(G2) Q3.1(G) R24.2 R25.2 R26.2
+5V: D10.2(A)
GND: C11.2 C65.2 D6.3(GND) D6.8(GND) D7.3(GND) D7.8(GND) D11.2 P5.2(GND) P5.5(GND) P5.8(GND) P5.11(GND) P5.17(GND) P5.20 P5.21 P5.22 P5.23 Q5.2(S) R31.1
DDI_B_HPD: Q3.2(S) R26.1
DDI_B_SCL: Q1.1(S1) R24.1
DDI_B_SDA: Q1.4(S2) R25.1
DDI_B_TX0_N: C27.2
DDI_B_TX0_P: C26.2
DDI_B_TX1_N: C29.2
DDI_B_TX1_P: C28.2
DDI_B_TX2_N: C31.2
DDI_B_TX2_P: C30.2
DDI_B_TX3_N: C33.2
DDI_B_TX3_P: C32.2
SLS_S0: R23.2
TMDS_CK_N: C33.1 D7.5(D2-) D7.6(NC) P5.12(TMDS_CLK-) R55.2
TMDS_CK_P: C32.1 D7.4(D2+) D7.7(NC) P5.10(TMDS_CLK+) R53.2
TMDS_D0_N: C31.1 D7.2(D1-) D7.9(NC) P5.9(TMDS_D0-) R51.2
TMDS_D0_P: C30.1 D7.1(D1+) D7.10(NC) P5.7(TMDS_D0+) R14.2
TMDS_D1_N: C29.1 D6.5(D2-) D6.6(NC) P5.6(TMDS_D1-) R56.1
TMDS_D1_P: C28.1 D6.4(D2+) D6.7(NC) P5.4(TMDS_D1+) R54.1
TMDS_D2_N: C27.1 D6.2(D1-) D6.9(NC) P5.3(TMDS_D2-) R52.1
TMDS_D2_P: C26.1 D6.1(D1+) D6.10(NC) P5.1(TMDS_D2+) R15.1
TMDS_HPD: D11.3 P5.19(HEC_DATA+) R29.1
TMDS_SCL: D11.5 P5.15(DDC_SCL) Q1.6(D1) R27.1
TMDS_SDA: D11.4 P5.16(DDC_SDA) Q1.3(D2) R28.1
NetQ3_3: Q3.3(D) R29.2 R31.2
NetQ5_1: Q5.1(G) R23.1
NetQ5_3: Q5.3(D) R14.1 R15.2 R51.1 R52.2 R53.1 R54.2 R55.1 R56.2

Not connected (* = marked no-connect by the designer): D11 1; P5 13(CEC)* 14(HEC_DATA-)*

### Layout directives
differential pair; net class HSIO: TMDS_CK_N, TMDS_CK_P, TMDS_D0_N, TMDS_D0_P, TMDS_D1_N, TMDS_D1_P, TMDS_D2_N, TMDS_D2_P

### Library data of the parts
C11 C26-C33 C65 = C1005-0402: Value: 1uF
D6 D7 = TPD4E05U06
D10 = Schottky Diode
Q3 Q5 = AO3400A: N-Channel MOSFET
R14 R15 R23-R29 R31 R51-R56 = R1005-0402: Resistor

## Sheet SXM-PCIE.SchDoc
size A4; SheetNumber: 7; SheetTotal: 8
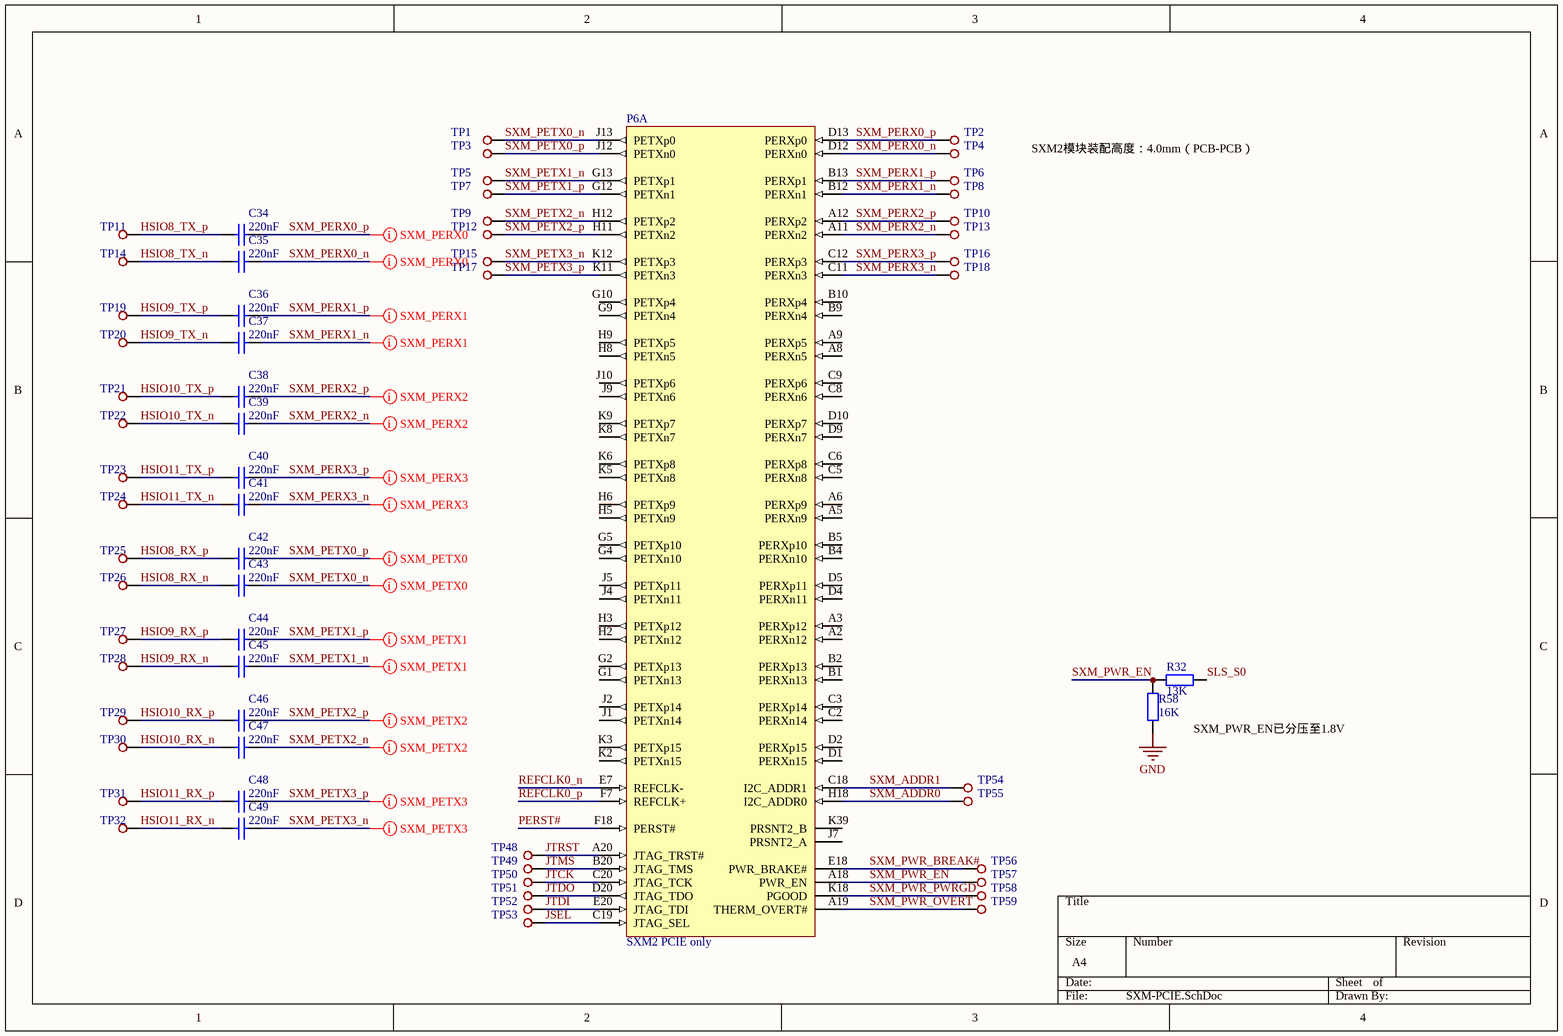
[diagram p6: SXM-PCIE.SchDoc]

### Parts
C34  220nF  [C1005-0402]
C35  220nF  [C1005-0402]
C36  220nF  [C1005-0402]
C37  220nF  [C1005-0402]
C38  220nF  [C1005-0402]
C39  220nF  [C1005-0402]
C40  220nF  [C1005-0402]
C41  220nF  [C1005-0402]
C42  220nF  [C1005-0402]
C43  220nF  [C1005-0402]
C44  220nF  [C1005-0402]
C45  220nF  [C1005-0402]
C46  220nF  [C1005-0402]
C47  220nF  [C1005-0402]
C48  220nF  [C1005-0402]
C49  220nF  [C1005-0402]
P6  SXM2 PCIE only  [SXM2_PCIEonly]  (part A of 3)
R32  13K  [R1005-0402]
R58  16K  [R1005-0402]
TP1  TestPoint  [TP_HS]  (value not drawn)
TP2  TestPoint  [TP_HS]  (value not drawn)
TP3  TestPoint  [TP_HS]  (value not drawn)
TP4  TestPoint  [TP_HS]  (value not drawn)
TP5  TestPoint  [TP_HS]  (value not drawn)
TP6  TestPoint  [TP_HS]  (value not drawn)
TP7  TestPoint  [TP_HS]  (value not drawn)
TP8  TestPoint  [TP_HS]  (value not drawn)
TP9  TestPoint  [TP_HS]  (value not drawn)
TP10  TestPoint  [TP_HS]  (value not drawn)
TP11  TestPoint  [TP_HS]  (value not drawn)
TP12  TestPoint  [TP_HS]  (value not drawn)
TP13  TestPoint  [TP_HS]  (value not drawn)
TP14  TestPoint  [TP_HS]  (value not drawn)
TP15  TestPoint  [TP_HS]  (value not drawn)
TP16  TestPoint  [TP_HS]  (value not drawn)
TP17  TestPoint  [TP_HS]  (value not drawn)
TP18  TestPoint  [TP_HS]  (value not drawn)
TP19  TestPoint  [TP_HS]  (value not drawn)
TP20  TestPoint  [TP_HS]  (value not drawn)
TP21  TestPoint  [TP_HS]  (value not drawn)
TP22  TestPoint  [TP_HS]  (value not drawn)
TP23  TestPoint  [TP_HS]  (value not drawn)
TP24  TestPoint  [TP_HS]  (value not drawn)
TP25  TestPoint  [TP_HS]  (value not drawn)
TP26  TestPoint  [TP_HS]  (value not drawn)
TP27  TestPoint  [TP_HS]  (value not drawn)
TP28  TestPoint  [TP_HS]  (value not drawn)
TP29  TestPoint  [TP_HS]  (value not drawn)
TP30  TestPoint  [TP_HS]  (value not drawn)
TP31  TestPoint  [TP_HS]  (value not drawn)
TP32  TestPoint  [TP_HS]  (value not drawn)
TP48  TestPoint  [TP_50mil]  (value not drawn)
TP49  TestPoint  [TP_50mil]  (value not drawn)
TP50  TestPoint  [TP_50mil]  (value not drawn)
TP51  TestPoint  [TP_50mil]  (value not drawn)
TP52  TestPoint  [TP_50mil]  (value not drawn)
TP53  TestPoint  [TP_50mil]  (value not drawn)
TP54  TestPoint  [TP_50mil]  (value not drawn)
TP55  TestPoint  [TP_50mil]  (value not drawn)
TP56  TestPoint  [TP_50mil]  (value not drawn)
TP57  TestPoint  [TP_50mil]  (value not drawn)
TP58  TestPoint  [TP_50mil]  (value not drawn)
TP59  TestPoint  [TP_50mil]  (value not drawn)

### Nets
GND: R58.2
HSIO8_RX_n: C43.2 TP26.1
HSIO8_RX_p: C42.2 TP25.1
HSIO8_TX_n: C35.2 TP14.1
HSIO8_TX_p: C34.2 TP11.1
HSIO9_RX_n: C45.2 TP28.1
HSIO9_RX_p: C44.2 TP27.1
HSIO9_TX_n: C37.2 TP20.1
HSIO9_TX_p: C36.2 TP19.1
HSIO10_RX_n: C47.2 TP30.1
HSIO10_RX_p: C46.2 TP29.1
HSIO10_TX_n: C39.2 TP22.1
HSIO10_TX_p: C38.2 TP21.1
HSIO11_RX_n: C49.2 TP32.1
HSIO11_RX_p: C48.2 TP31.1
HSIO11_TX_n: C41.2 TP24.1
HSIO11_TX_p: C40.2 TP23.1
JSEL: P6.C19(JTAG_SEL) TP53.1
JTCK: P6.C20(JTAG_TCK) TP50.1
JTDI: P6.E20(JTAG_TDI) TP52.1
JTDO: P6.D20(JTAG_TDO) TP51.1
JTMS: P6.B20(JTAG_TMS) TP49.1
JTRST: P6.A20(JTAG_TRST#) TP48.1
PERST#: P6.F18(PERST#)
REFCLK0_n: P6.E7(REFCLK-)
REFCLK0_p: P6.F7(REFCLK+)
SLS_S0: R32.1
SXM_ADDR0: P6.H18(I2C_ADDR0) TP55.1
SXM_ADDR1: P6.C18(I2C_ADDR1) TP54.1
SXM_PERX0_n: C35.1 P6.D12(PERXn0) TP4.1
SXM_PERX0_p: C34.1 P6.D13(PERXp0) TP2.1
SXM_PERX1_n: C37.1 P6.B12(PERXn1) TP8.1
SXM_PERX1_p: C36.1 P6.B13(PERXp1) TP6.1
SXM_PERX2_n: C39.1 P6.A11(PERXn2) TP13.1
SXM_PERX2_p: C38.1 P6.A12(PERXp2) TP10.1
SXM_PERX3_n: C41.1 P6.C11(PERXn3) TP18.1
SXM_PERX3_p: C40.1 P6.C12(PERXp3) TP16.1
SXM_PETX0_n: C43.1 P6.J13(PETXp0) TP1.1
SXM_PETX0_p: C42.1 P6.J12(PETXn0) TP3.1
SXM_PETX1_n: C45.1 P6.G13(PETXp1) TP5.1
SXM_PETX1_p: C44.1 P6.G12(PETXn1) TP7.1
SXM_PETX2_n: C47.1 P6.H12(PETXp2) TP9.1
SXM_PETX2_p: C46.1 P6.H11(PETXn2) TP12.1
SXM_PETX3_n: C49.1 P6.K12(PETXp3) TP15.1
SXM_PETX3_p: C48.1 P6.K11(PETXn3) TP17.1
SXM_PWR_BREAK#: P6.E18(PWR_BRAKE#) TP56.1
SXM_PWR_EN: P6.A18(PWR_EN) R32.2 R58.1 TP57.1
SXM_PWR_OVERT: P6.A19(THERM_OVERT#) TP59.1
SXM_PWR_PWRGD: P6.K18(PGOOD) TP58.1

Not connected (* = marked no-connect by the designer): P6 A2(PERXn12) A3(PERXp12) A5(PERXn9) A6(PERXp9) A8(PERXn5) A9(PERXp5) B1(PERXn13) B2(PERXp13) B4(PERXn10) B5(PERXp10) B9(PERXn4) B10(PERXp4) C2(PERXn14) C3(PERXp14) C5(PERXn8) C6(PERXp8) C8(PERXn6) C9(PERXp6) D1(PERXn15) D2(PERXp15) D4(PERXn11) D5(PERXp11) D9(PERXn7) D10(PERXp7) G1(PETXn13) G2(PETXp13) G4(PETXn10) G5(PETXp10) G9(PETXn4) G10(PETXp4) H2(PETXn12) H3(PETXp12) H5(PETXn9) H6(PETXp9) H8(PETXn5) H9(PETXp5) J1(PETXn14) J2(PETXp14) J4(PETXn11) J5(PETXp11) J7(PRSNT2_A) J9(PETXn6) J10(PETXp6) K2(PETXn15) K3(PETXp15) K5(PETXn8) K6(PETXp8) K8(PETXn7) K9(PETXp7) K39(PRSNT2_B)

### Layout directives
differential pair: SXM_PERX0_n, SXM_PERX0_p, SXM_PERX1_n, SXM_PERX1_p, SXM_PERX2_n, SXM_PERX2_p, SXM_PERX3_n, SXM_PERX3_p, SXM_PETX0_n, SXM_PETX0_p, SXM_PETX1_n, SXM_PETX1_p, SXM_PETX2_n, SXM_PETX2_p, SXM_PETX3_n, SXM_PETX3_p
net class HSIO: SXM_PERX0_n, SXM_PERX0_p, SXM_PERX1_n, SXM_PERX1_p, SXM_PERX2_n, SXM_PERX2_p, SXM_PERX3_n, SXM_PERX3_p, SXM_PETX0_n, SXM_PETX0_p, SXM_PETX1_n, SXM_PETX1_p, SXM_PETX2_n, SXM_PETX2_p, SXM_PETX3_n, SXM_PETX3_p

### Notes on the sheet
- SXM2模块装配高度：4.0mm（PCB-PCB）
- SXM_PWR_EN已分压至1.8V

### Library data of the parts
C34-C49 = C1005-0402: Value: 1uF
P6 = SXM2-PCIEonly
R32 R58 = R1005-0402: Resistor
TP1-TP32 = TestPoint_HS

## Sheet SXM-Power.SchDoc
size A4 portrait; SheetNumber: 9; SheetTotal: 10
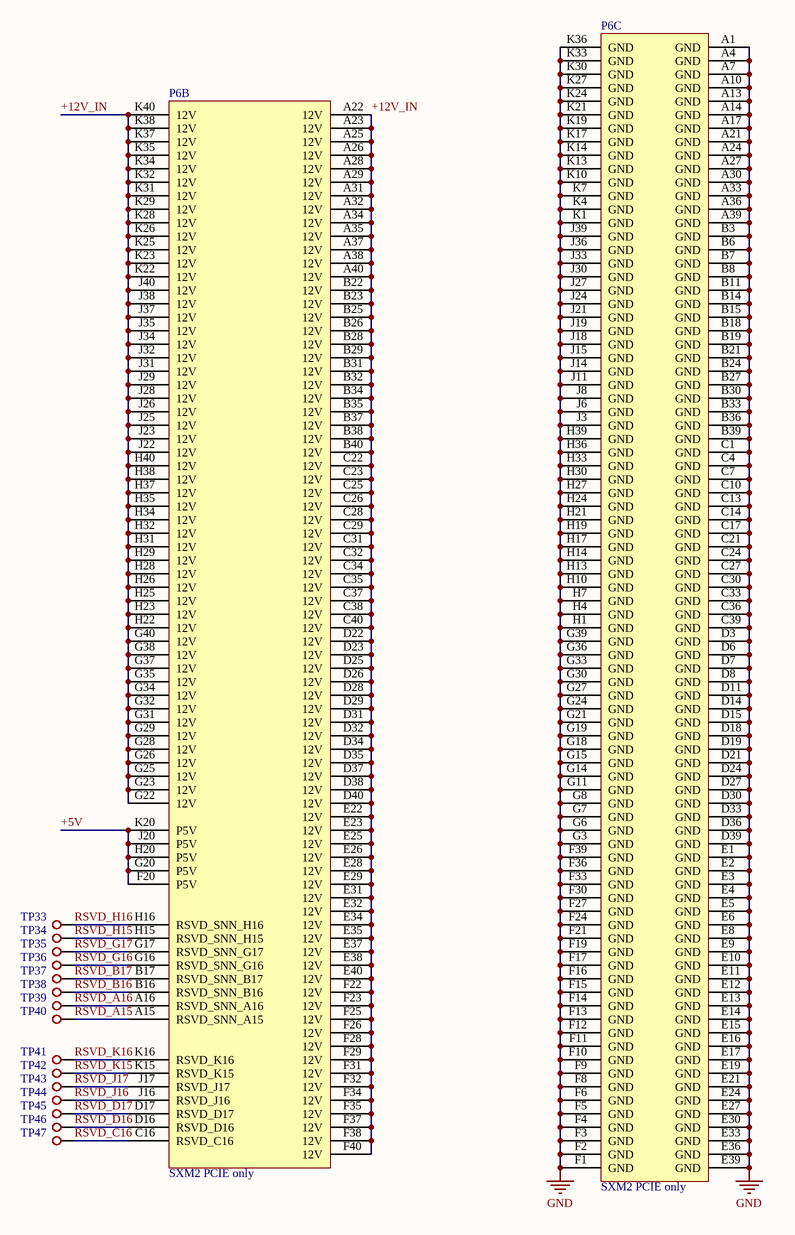
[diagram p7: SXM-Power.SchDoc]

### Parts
P6  SXM2 PCIE only  [SXM2_PCIEonly]  (parts B,C of 3)
TP33  TestPoint  [TP_50mil]  (value not drawn)
TP34  TestPoint  [TP_50mil]  (value not drawn)
TP35  TestPoint  [TP_50mil]  (value not drawn)
TP36  TestPoint  [TP_50mil]  (value not drawn)
TP37  TestPoint  [TP_50mil]  (value not drawn)
TP38  TestPoint  [TP_50mil]  (value not drawn)
TP39  TestPoint  [TP_50mil]  (value not drawn)
TP40  TestPoint  [TP_50mil]  (value not drawn)
TP41  TestPoint  [TP_50mil]  (value not drawn)
TP42  TestPoint  [TP_50mil]  (value not drawn)
TP43  TestPoint  [TP_50mil]  (value not drawn)
TP44  TestPoint  [TP_50mil]  (value not drawn)
TP45  TestPoint  [TP_50mil]  (value not drawn)
TP46  TestPoint  [TP_50mil]  (value not drawn)
TP47  TestPoint  [TP_50mil]  (value not drawn)

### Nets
+5V: P6.F20(P5V) P6.G20(P5V) P6.H20(P5V) P6.J20(P5V) P6.K20(P5V)
+12V_IN: P6.A22(12V) P6.A23(12V) P6.A25(12V) P6.A26(12V) P6.A28(12V) P6.A29(12V) P6.A31(12V) P6.A32(12V) P6.A34(12V) P6.A35(12V) P6.A37(12V) P6.A38(12V) P6.A40(12V) P6.B22(12V) P6.B23(12V) P6.B25(12V) P6.B26(12V) P6.B28(12V) P6.B29(12V) P6.B31(12V) P6.B32(12V) P6.B34(12V) P6.B35(12V) P6.B37(12V) P6.B38(12V) P6.B40(12V) P6.C22(12V) P6.C23(12V) P6.C25(12V) P6.C26(12V) P6.C28(12V) P6.C29(12V) P6.C31(12V) P6.C32(12V) P6.C34(12V) P6.C35(12V) P6.C37(12V) P6.C38(12V) P6.C40(12V) P6.D22(12V) P6.D23(12V) P6.D25(12V) P6.D26(12V) P6.D28(12V) P6.D29(12V) P6.D31(12V) P6.D32(12V) P6.D34(12V) P6.D35(12V) P6.D37(12V) P6.D38(12V) P6.D40(12V) P6.E22(12V) P6.E23(12V) P6.E25(12V) P6.E26(12V) P6.E28(12V) P6.E29(12V) P6.E31(12V) P6.E32(12V) P6.E34(12V) P6.E35(12V) P6.E37(12V) P6.E38(12V) P6.E40(12V) P6.F22(12V) P6.F23(12V) P6.F25(12V) P6.F26(12V) P6.F28(12V) P6.F29(12V) P6.F31(12V) P6.F32(12V) P6.F34(12V) P6.F35(12V) P6.F37(12V) P6.F38(12V) P6.F40(12V) P6.G22(12V) P6.G23(12V) P6.G25(12V) P6.G26(12V) P6.G28(12V) P6.G29(12V) P6.G31(12V) P6.G32(12V) P6.G34(12V) P6.G35(12V) P6.G37(12V) P6.G38(12V) P6.G40(12V) P6.H22(12V) P6.H23(12V) P6.H25(12V) P6.H26(12V) P6.H28(12V) P6.H29(12V) P6.H31(12V) P6.H32(12V) P6.H34(12V) P6.H35(12V) P6.H37(12V) P6.H38(12V) P6.H40(12V) P6.J22(12V) P6.J23(12V) P6.J25(12V) P6.J26(12V) P6.J28(12V) P6.J29(12V) P6.J31(12V) P6.J32(12V) P6.J34(12V) P6.J35(12V) P6.J37(12V) P6.J38(12V) P6.J40(12V) P6.K22(12V) P6.K23(12V) P6.K25(12V) P6.K26(12V) P6.K28(12V) P6.K29(12V) P6.K31(12V) P6.K32(12V) P6.K34(12V) P6.K35(12V) P6.K37(12V) P6.K38(12V) P6.K40(12V)
GND: P6.A1(GND) P6.A4(GND) P6.A7(GND) P6.A10(GND) P6.A13(GND) P6.A14(GND) P6.A17(GND) P6.A21(GND) P6.A24(GND) P6.A27(GND) P6.A30(GND) P6.A33(GND) P6.A36(GND) P6.A39(GND) P6.B3(GND) P6.B6(GND) P6.B7(GND) P6.B8(GND) P6.B11(GND) P6.B14(GND) P6.B15(GND) P6.B18(GND) P6.B19(GND) P6.B21(GND) P6.B24(GND) P6.B27(GND) P6.B30(GND) P6.B33(GND) P6.B36(GND) P6.B39(GND) P6.C1(GND) P6.C4(GND) P6.C7(GND) P6.C10(GND) P6.C13(GND) P6.C14(GND) P6.C17(GND) P6.C21(GND) P6.C24(GND) P6.C27(GND) P6.C30(GND) P6.C33(GND) P6.C36(GND) P6.C39(GND) P6.D3(GND) P6.D6(GND) P6.D7(GND) P6.D8(GND) P6.D11(GND) P6.D14(GND) P6.D15(GND) P6.D18(GND) P6.D19(GND) P6.D21(GND) P6.D24(GND) P6.D27(GND) P6.D30(GND) P6.D33(GND) P6.D36(GND) P6.D39(GND) P6.E1(GND) P6.E2(GND) P6.E3(GND) P6.E4(GND) P6.E5(GND) P6.E6(GND) P6.E8(GND) P6.E9(GND) P6.E10(GND) P6.E11(GND) P6.E12(GND) P6.E13(GND) P6.E14(GND) P6.E15(GND) P6.E16(GND) P6.E17(GND) P6.E19(GND) P6.E21(GND) P6.E24(GND) P6.E27(GND) P6.E30(GND) P6.E33(GND) P6.E36(GND) P6.E39(GND) P6.F1(GND) P6.F2(GND) P6.F3(GND) P6.F4(GND) P6.F5(GND) P6.F6(GND) P6.F8(GND) P6.F9(GND) P6.F10(GND) P6.F11(GND) P6.F12(GND) P6.F13(GND) P6.F14(GND) P6.F15(GND) P6.F16(GND) P6.F17(GND) P6.F19(GND) P6.F21(GND) P6.F24(GND) P6.F27(GND) P6.F30(GND) P6.F33(GND) P6.F36(GND) P6.F39(GND) P6.G3(GND) P6.G6(GND) P6.G7(GND) P6.G8(GND) P6.G11(GND) P6.G14(GND) P6.G15(GND) P6.G18(GND) P6.G19(GND) P6.G21(GND) P6.G24(GND) P6.G27(GND) P6.G30(GND) P6.G33(GND) P6.G36(GND) P6.G39(GND) P6.H1(GND) P6.H4(GND) P6.H7(GND) P6.H10(GND) P6.H13(GND) P6.H14(GND) P6.H17(GND) P6.H19(GND) P6.H21(GND) P6.H24(GND) P6.H27(GND) P6.H30(GND) P6.H33(GND) P6.H36(GND) P6.H39(GND) P6.J3(GND) P6.J6(GND) P6.J8(GND) P6.J11(GND) P6.J14(GND) P6.J15(GND) P6.J18(GND) P6.J19(GND) P6.J21(GND) P6.J24(GND) P6.J27(GND) P6.J30(GND) P6.J33(GND) P6.J36(GND) P6.J39(GND) P6.K1(GND) P6.K4(GND) P6.K7(GND) P6.K10(GND) P6.K13(GND) P6.K14(GND) P6.K17(GND) P6.K19(GND) P6.K21(GND) P6.K24(GND) P6.K27(GND) P6.K30(GND) P6.K33(GND) P6.K36(GND)
RSVD_A15: P6.A15(RSVD_SNN_A15) TP40.1
RSVD_A16: P6.A16(RSVD_SNN_A16) TP39.1
RSVD_B16: P6.B16(RSVD_SNN_B16) TP38.1
RSVD_B17: P6.B17(RSVD_SNN_B17) TP37.1
RSVD_C16: P6.C16(RSVD_C16) TP47.1
RSVD_D16: P6.D16(RSVD_D16) TP46.1
RSVD_D17: P6.D17(RSVD_D17) TP45.1
RSVD_G16: P6.G16(RSVD_SNN_G16) TP36.1
RSVD_G17: P6.G17(RSVD_SNN_G17) TP35.1
RSVD_H15: P6.H15(RSVD_SNN_H15) TP34.1
RSVD_H16: P6.H16(RSVD_SNN_H16) TP33.1
RSVD_J16: P6.J16(RSVD_J16) TP44.1
RSVD_J17: P6.J17(RSVD_J17) TP43.1
RSVD_K15: P6.K15(RSVD_K15) TP42.1
RSVD_K16: P6.K16(RSVD_K16) TP41.1

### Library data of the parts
P6 = SXM2-PCIEonly

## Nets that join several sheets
+3V3: N100-Core (R16.1), M.2-PCIE (12 pins), PMU (6 pins), GbE (8 pins), DP-HDMI (7 pins)
+3V3_SB: N100-Core (D1.2 R46.1 R50.1), PMU (C58.1 U5.2)
+5V: PMU (5 pins), USB (6 pins), DP-HDMI (D10.2), SXM-Power (5 pins)
+12V_CPU: N100-Core (11 pins), PMU (D12.1 D13.1)
+12V_IN: PMU (21 pins), SXM-Power (130 pins)
GND: N100-Core (79 pins), M.2-PCIE (19 pins), PMU (43 pins), GbE (16 pins), USB (28 pins), DP-HDMI (18 pins), SXM-PCIE (R58.2), SXM-Power (168 pins)
CLKREQ4: N100-Core (M1.102), GbE (R5.2)
CPU_FAN_PWM: N100-Core (M1.2), PMU (R22.2)
CPU_FAN_TAC: N100-Core (M1.4), PMU (C10.2 R21.2 R59.1)
DDI_B_HPD: N100-Core (M1.183), DP-HDMI (Q3.2 R26.1)
DDI_B_SCL: N100-Core (M1.171), DP-HDMI (Q1.1 R24.1)
DDI_B_SDA: N100-Core (M1.169), DP-HDMI (Q1.4 R25.1)
DDI_B_TX0_N: N100-Core (M1.215), DP-HDMI (C27.2)
DDI_B_TX0_P: N100-Core (M1.217), DP-HDMI (C26.2)
DDI_B_TX1_N: N100-Core (M1.209), DP-HDMI (C29.2)
DDI_B_TX1_P: N100-Core (M1.211), DP-HDMI (C28.2)
DDI_B_TX2_N: N100-Core (M1.203), DP-HDMI (C31.2)
DDI_B_TX2_P: N100-Core (M1.205), DP-HDMI (C30.2)
DDI_B_TX3_N: N100-Core (M1.197), DP-HDMI (C33.2)
DDI_B_TX3_P: N100-Core (M1.199), DP-HDMI (C32.2)
HSIO2_RX_n: N100-Core (M1.30), M.2-PCIE (P1.31 TP69.1)
HSIO2_RX_p: N100-Core (M1.28), M.2-PCIE (P1.29 TP66.1)
HSIO2_TX_n: N100-Core (M1.27), M.2-PCIE (C4.2 TP70.1)
HSIO2_TX_p: N100-Core (M1.25), M.2-PCIE (C3.2 TP68.1)
HSIO3_RX_n: N100-Core (M1.36), M.2-PCIE (P1.43 TP75.1)
HSIO3_RX_p: N100-Core (M1.34), M.2-PCIE (P1.41 TP72.1)
HSIO3_TX_n: N100-Core (M1.33), M.2-PCIE (C6.2 TP76.1)
HSIO3_TX_p: N100-Core (M1.31), M.2-PCIE (C5.2 TP74.1)
HSIO6_RX_n: N100-Core (M1.66), GbE (P2.41 TP84.1)
HSIO6_RX_p: N100-Core (M1.64), GbE (P2.43 TP85.1)
HSIO6_TX_n: N100-Core (M1.63), GbE (C63.2 TP80.1)
HSIO6_TX_p: N100-Core (M1.61), GbE (C64.2 TP83.1)
HSIO8_RX_n: N100-Core (M1.42), SXM-PCIE (C43.2 TP26.1)
HSIO8_RX_p: N100-Core (M1.40), SXM-PCIE (C42.2 TP25.1)
HSIO8_TX_n: N100-Core (M1.39), SXM-PCIE (C35.2 TP14.1)
HSIO8_TX_p: N100-Core (M1.37), SXM-PCIE (C34.2 TP11.1)
HSIO9_RX_n: N100-Core (M1.48), SXM-PCIE (C45.2 TP28.1)
HSIO9_RX_p: N100-Core (M1.46), SXM-PCIE (C44.2 TP27.1)
HSIO9_TX_n: N100-Core (M1.45), SXM-PCIE (C37.2 TP20.1)
HSIO9_TX_p: N100-Core (M1.43), SXM-PCIE (C36.2 TP19.1)
HSIO10_RX_n: N100-Core (M1.54), SXM-PCIE (C47.2 TP30.1)
HSIO10_RX_p: N100-Core (M1.52), SXM-PCIE (C46.2 TP29.1)
HSIO10_TX_n: N100-Core (M1.51), SXM-PCIE (C39.2 TP22.1)
HSIO10_TX_p: N100-Core (M1.49), SXM-PCIE (C38.2 TP21.1)
HSIO11_RX_n: N100-Core (M1.60), SXM-PCIE (C49.2 TP32.1)
HSIO11_RX_p: N100-Core (M1.58), SXM-PCIE (C48.2 TP31.1)
HSIO11_TX_n: N100-Core (M1.57), SXM-PCIE (C41.2 TP24.1)
HSIO11_TX_p: N100-Core (M1.55), SXM-PCIE (C40.2 TP23.1)
PERST#: N100-Core (M1.105), M.2-PCIE (P1.50), GbE (P2.52 TP61.1), SXM-PCIE (P6.F18)
REFCLK0_n: N100-Core (M1.87), SXM-PCIE (P6.E7)
REFCLK0_p: N100-Core (M1.85), SXM-PCIE (P6.F7)
REFCLK1_n: N100-Core (M1.93), M.2-PCIE (P1.55 TP79.1)
REFCLK1_p: N100-Core (M1.91), M.2-PCIE (P1.53 TP78.1)
REFCLK2_n: N100-Core (M1.99), GbE (P2.47 TP86.1)
REFCLK2_p: N100-Core (M1.97), GbE (P2.49 TP87.1)
SLS_S0: N100-Core (M1.5 R48.1), PMU (R30.2), DP-HDMI (R23.2), SXM-PCIE (R32.1)
SUSCLK: N100-Core (M1.131), GbE (R41.1)
SYS_FAN_PWM: N100-Core (M1.6), PMU (R9.2)
SYS_FAN_TAC: N100-Core (M1.8), PMU (C9.2 R8.2 R57.1)
USB_1_n: N100-Core (M1.73), USB (D2.2 D2.9 P4.2)
USB_1_p: N100-Core (M1.75), USB (D2.1 D2.10 P4.3)
USB_2_n: N100-Core (M1.67), USB (D2.5 D2.6 P4.11)
USB_2_p: N100-Core (M1.69), USB (D2.4 D2.7 P4.12)
USB_3_n: N100-Core (M1.79), USB (D3.1 D3.10 P3.2)
USB_3_p: N100-Core (M1.81), USB (D3.2 D3.9 P3.3)
USB_4_n: N100-Core (M1.72), USB (D3.4 D3.7 P3.6)
USB_4_p: N100-Core (M1.70), USB (D3.5 D3.6 P3.7)
USB_F1_n: N100-Core (M1.109), USB (D15.2 D15.9 JUSB.4)
USB_F1_p: N100-Core (M1.111), USB (D15.1 D15.10 JUSB.6)
USB_F2_n: N100-Core (M1.114), USB (D15.4 D15.7 JUSB.3)
USB_F2_p: N100-Core (M1.112), USB (D15.5 D15.6 JUSB.5)
USB_M2_n: N100-Core (M1.78), GbE (P2.5)
USB_M2_p: N100-Core (M1.76), GbE (P2.3)
USBSS_1_RX_n: N100-Core (M1.18), USB (D5.4 D5.7 P4.5)
USBSS_1_RX_p: N100-Core (M1.16), USB (D5.5 D5.6 P4.6)
USBSS_1_TX_n: N100-Core (M1.15), USB (C14.2)
USBSS_1_TX_p: N100-Core (M1.13), USB (C15.2)
USBSS_2_RX_n: N100-Core (M1.24), USB (D5.1 D5.10 P4.14)
USBSS_2_RX_p: N100-Core (M1.22), USB (D5.2 D5.9 P4.15)
USBSS_2_TX_n: N100-Core (M1.21), USB (C17.2)
USBSS_2_TX_p: N100-Core (M1.19), USB (C18.2)
WAKE#: N100-Core (M1.103), M.2-PCIE (R45.1), GbE (P2.55 TP65.1)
